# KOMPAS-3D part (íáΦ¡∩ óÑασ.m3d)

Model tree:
1. Эскиз:1
2. Операция выдавливания:1
     Расстояние 1 = 44.4; Расстояние 2 = 1
3. Эскиз:2
4. Вырезать элемент выдавливания:1
     Расстояние 2 = 78.9484; Расстояние 1 = 82.0723
5. Эскиз:3
6. Вырезать элемент выдавливания:2
     Расстояние 2 = 91.3176
7. Отрезок:1
     Точка 1. Координата X = -111.834; Точка 1. Координата Z = 30.8074; Точка 2. Координата X = 81.42; Точка 2. Координата Y = -0.789388; Точка 2. Координата Z = 162.608; Длина отрезка = 233.921
8. Перпендикулярная плоскость:1
9. Эскиз:4
10. Вырезать кинематический элемент:2
     Толщина стенки 1 = 1; Толщина стенки 2 = 1
11. Эскиз:5
12. Вырезать элемент выдавливания:3
     Расстояние 2 = 50.0285; Расстояние 1 = 54; Угол 1 = 11
13. Эскиз:6
14. Вырезать элемент выдавливания:4
     Расстояние 2 = 50.0285; Расстояние 1 = 0.5
15. Скругление:6
     Радиус = 2; Хорда = 3
16. Скругление:11
     Радиус = 0.1; Хорда = 3
17. Скругление:12
     Радиус = 1; Хорда = 3
18. Эскиз:7
19. Операция выдавливания:2
     Расстояние 1 = 34
20. Скругление:13
     Радиус = 1; Хорда = 3
21. Скругление:14
     Радиус = 1; Хорда = 3
22. Скругление:15
     Радиус = 0.5; Хорда = 3
23. Скругление:16
     Радиус = 0.3; Хорда = 3
24. Скругление:17
     Радиус = 1; Хорда = 3
25. Зеркальный массив:2  (with: Операция выдавливания:1, Вырезать элемент выдавливания:1, Вырезать элемент выдавливания:2, Вырезать кинематический элемент:2, Вырезать элемент выдавливания:3, Вырезать элемент выдавливания:4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)  (labels: Экземпляр ( 1 ); Экземпляр ( 2 ))
26. Смещенная плоскость:1
     Расстояние = 44.5
27. Эскиз:8
28. Операция выдавливания:3
     Расстояние 1 = 34; Расстояние 2 = 13; Угол 2 = 20
29. Эскиз:9
30. Вырезать элемент выдавливания:5
     Расстояние 1 = 14
31. Скругление:21
     Радиус = 0.6; Хорда = 3
32. Эскиз:10
33. Вырезать элемент выдавливания:6
     Расстояние 1 = 44.5
34. Скругление:23
     Радиус = 1; Хорда = 0.3
35. Эскиз:12
36. Вырезать элемент выдавливания:7
     Расстояние 1 = 22
37. Эскиз:13
38. Вырезать элемент выдавливания:8
     Расстояние 1 = 13; Угол 1 = 76
39. Эскиз:14
40. Вырезать элемент выдавливания:9
     Расстояние 1 = 34
41. Эскиз:15
42. Вырезать элемент выдавливания:10
     Расстояние 1 = 0.5
43. Скругление:24
     Радиус = 2; Хорда = 3
44. Скругление:25
     Радиус = 2; Хорда = 3
45. Эскиз:19
46. Операция выдавливания:4
     Расстояние 1 = 1.5; Расстояние 2 = 1
47. Скругление:26
     Радиус = 0.5
48. Эскиз:20
49. Вырезать элемент выдавливания:11
     Расстояние 1 = 0.5
50. Эскиз:21
51. Вырезать элемент выдавливания:12
     Расстояние 1 = 0.5
52. Эскиз:22
53. Операция выдавливания:5
     Расстояние 1 = 1.5; Расстояние 2 = 1
54. Скругление:27
     Радиус = 0.5; Хорда = 3
55. Смещенная плоскость:2
     Расстояние = 15
56. Эскиз:24
57. Вырезать элемент выдавливания:13
     Расстояние 2 = 1; Расстояние 1 = 31.5
58. Эскиз:25
59. Вырезать элемент выдавливания:14
     Расстояние 2 = 1; Расстояние 1 = 0.5
60. Эскиз:26
61. Операция выдавливания:6
     Расстояние 1 = 1.5; Расстояние 2 = 1
62. Скругление:28
     Радиус = 0.5; Хорда = 3
63. Скругление:29
     Радиус = 0.5; Хорда = 3
64. Скругление:30
     Радиус = 0.5; Хорда = 3
65. Эскиз:27
66. Вырезать элемент выдавливания:15
     Расстояние 2 = 1; Расстояние 1 = 0.5
67. Эскиз:28
68. Вырезать элемент выдавливания:16
     Расстояние 2 = 1; Расстояние 1 = 1.5
69. Эскиз:29
70. Операция выдавливания:7
     Расстояние 1 = 1; Расстояние 2 = 1
71. Скругление:31
     Радиус = 1; Хорда = 3
72. Эскиз:30
73. Вырезать элемент выдавливания:17
     Расстояние 2 = 1; Расстояние 1 = 0.5
74. Эскиз:31
75. Вырезать элемент выдавливания:18
     Расстояние 2 = 1; Расстояние 1 = 40.5
76. Скругление:32
     Радиус = 1; Хорда = 0.3
77. Эскиз:32
78. Вырезать элемент выдавливания:19
     Расстояние 2 = 1; Расстояние 1 = 0.2
79. Скругление:34
     Радиус = 0.5; Хорда = 3
80. Эскиз:33
81. Операция выдавливания:8
     Расстояние 1 = 1.5; Расстояние 2 = 1
82. Скругление:35
     Радиус = 0.5; Хорда = 3
83. Эскиз:34
84. Вырезать элемент выдавливания:20
     Расстояние 2 = 1; Расстояние 1 = 0.5
85. Эскиз:35
86. Операция выдавливания:9
     Расстояние 1 = 1.5; Расстояние 2 = 1
87. Эскиз:36
88. Вырезать элемент выдавливания:21
     Расстояние 2 = 1; Расстояние 1 = 0.5
89. Эскиз:37
90. Вырезать элемент выдавливания:22
     Расстояние 2 = 1; Расстояние 1 = 1
91. Эскиз:38
92. Вырезать элемент выдавливания:23
     Расстояние 2 = 1; Расстояние 1 = 0.5
93. Скругление:36
     Радиус = 0.5; Хорда = 3
94. Эскиз:42
95. Операция выдавливания:10
     Расстояние 1 = 1.5; Расстояние 2 = 1
96. Скругление:39
     Радиус = 0.5; Хорда = 3
97. Скругление:40
     Радиус = 0.5; Хорда = 3
98. Эскиз:45
99. Вырезать элемент выдавливания:24
     Расстояние 2 = 1; Расстояние 1 = 0.5
100. Эскиз:46
101. Вырезать элемент выдавливания:25
     Расстояние 2 = 1; Расстояние 1 = 0.5
102. Эскиз:47
103. Вырезать элемент выдавливания:26
     Расстояние 2 = 1; Расстояние 1 = 2
104. Массив по концентрической сетке:1  (with: Вырезать элемент выдавливания:26)  (labels: Экземпляр ( 1, 1 ); Экземпляр ( 1, 2 ); Экземпляр ( 1, 3 ); Экземпляр ( 1, 4 ))
     N 2 = 50; Шаг 2 = 360; Номер 2 = 1
105. Эскиз:48
106. Операция выдавливания:12
     Расстояние 1 = 1.5; Расстояние 2 = 1
107. Скругление:41
     Радиус = 0.5; Хорда = 3
108. Эскиз:49
109. Вырезать элемент выдавливания:27
     Расстояние 2 = 1; Расстояние 1 = 0.5
110. Эскиз:50
111. Операция выдавливания:13
     Расстояние 1 = 1.5; Расстояние 2 = 1
112. Скругление:42
     Радиус = 0.5; Хорда = 3
113. Эскиз:51
114. Вырезать элемент выдавливания:28
     Расстояние 2 = 1; Расстояние 1 = 0.5
115. Эскиз:52
116. Операция выдавливания:14
     Расстояние 1 = 1.5; Расстояние 2 = 1
117. Скругление:43
     Радиус = 0.5; Хорда = 3
118. Эскиз:53
119. Вырезать элемент выдавливания:29
     Расстояние 2 = 1; Расстояние 1 = 0.5
120. Эскиз:54
121. Операция выдавливания:15
     Расстояние 1 = 1.5; Расстояние 2 = 1
122. Скругление:44
     Радиус = 0.5; Хорда = 3
123. Эскиз:55
124. Вырезать элемент выдавливания:30
     Расстояние 2 = 1; Расстояние 1 = 0.5
125. Эскиз:56
126. Операция выдавливания:16
     Расстояние 1 = 1.5; Расстояние 2 = 1
127. Скругление:45
     Радиус = 0.5; Хорда = 3
128. Эскиз:57
129. Вырезать элемент выдавливания:31
     Расстояние 2 = 1; Расстояние 1 = 0.5
130. Скругление:46
     Радиус = 1; Хорда = 3
131. Эскиз:58
132. Операция выдавливания:17
     Расстояние 1 = 5
133. Скругление:47
     Радиус = 2
134. Эскиз:59
135. Вырезать элемент выдавливания:32
     Расстояние 1 = 128.5
136. Скругление:48
     Радиус = 0.3
137. Эскиз:64
138. Операция выдавливания:20
     Расстояние 1 = 3; Расстояние 2 = 4
139. Эскиз:65
140. Вырезать элемент выдавливания:33
     Расстояние 1 = 58.8477
141. Скругление:49
     Радиус = 1
142. Эскиз:66
143. Операция выдавливания:21
     Расстояние 1 = 3; Расстояние 2 = 4
144. Эскиз:67
145. Вырезать элемент выдавливания:34
     Расстояние 1 = 59.4537
146. Скругление:50
     Радиус = 1
147. Эскиз:68
148. Операция выдавливания:22
     Расстояние 1 = 0.5; Расстояние 2 = 3
149. Эскиз:70
150. Операция выдавливания:23
     Расстояние 1 = 3; Расстояние 2 = 3
151. Эскиз:71
152. Операция выдавливания:24
     Расстояние 1 = 3; Угол 1 = 8; Расстояние 2 = 3
153. Эскиз:72
154. Вырезать элемент выдавливания:36
     Расстояние 1 = 5

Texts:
  башня2
  Сплав АЛ8  ГОСТ 1583-93
  stalker61
  Экземпляр ( 1 )
  Экземпляр ( 2 )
